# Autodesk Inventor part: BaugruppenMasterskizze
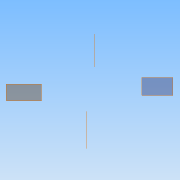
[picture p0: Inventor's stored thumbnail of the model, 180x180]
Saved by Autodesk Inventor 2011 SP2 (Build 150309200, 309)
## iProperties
Created: 2009-11
Part Number: BaugruppenMasterskizze
Document SubType Name: Modeling
Designer: gkramp
Density: 1 g/cm^3
d0: 1000,000 mm
d1: 900,000 mm
d3: 50,000 mm
d4: 80,000 mm
d5: 80,000 mm
d7: 90,000 mm
d8: 80,000 mm
d9: 80,000 mm
d10: 144,820 mm
d12: 90,00 grd
d13: 90,00 grd
d14: 90,00 grd
d15: 90,00 grd
Author: gkramp
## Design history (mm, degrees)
sketch "Skizze1"
  geometry: L1 (-450, -500)-(450, -500); L2 (450, -500)-(450, 500); L3 (450, 500)-(-450, 500); L4 (-450, 500)-(-450, -500); L5 (0, 23.685)-(0, -25.883) reference; L6 (-18.992, 0)-(22.934, 0) reference; L7 (-450, 500)-(-305.18, 355.18); L8 (450, 500)-(305.18, 355.18); L9 (-450, -500)-(-305.18, -355.18); L10 (-305.18, -355.18)-(305.18, -355.18); L11 (305.18, -355.18)-(450, -500); L12 (305.18, 355.18)-(305.18, -355.18); L13 (305.18, 355.18)-(-305.18, 355.18); L14 (-305.18, 355.18)-(-305.18, -355.18); 9 further points
  constraints: 24 end point, 4 perpendicular, 3 equal length, 3 horizontal, 2 parallel, 2 point on line, 12 other
  dimensions: "d0" = 1000 distance between parallel lines of L1 L3; "d1" = 900 distance between parallel lines of L2 L4; "d3" = 50 distance from line of L3 point (425, 450); "d4" = 80 distance of point (425, 370) point (425, 450); "d5" = 80 distance of point (425, 290) point (425, 370); "d6" = 290 distance of point (425, 0) point (425, 290) (derived); "d7" = 90 distance of point (425, 0) point (425, -90); "d8" = 80 distance of point (425, -170) point (425, -90); "d9" = 80 distance of point (425, -250) point (425, -170); "d10" = 144.82031 distance between parallel lines of L1 L10; "d11" = 45 deg angle of L1 L11 (derived); "d16" = 25 dimension on L2
workplane "Arbeitsebene1"
workplane "Arbeitsebene2"
workplane "Arbeitsebene3"
workplane "Arbeitsebene4"
node "Volumenkörpern"
node "Oberflächenkörpern"
other parameters: "d12" = 90 deg, "d13" = 90 deg, "d14" = 90 deg, "d15" = 90 deg
